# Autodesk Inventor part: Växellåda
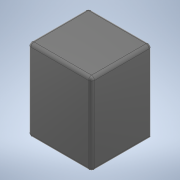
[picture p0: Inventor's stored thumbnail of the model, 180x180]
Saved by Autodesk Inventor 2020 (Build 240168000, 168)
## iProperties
Created: 2019-06
Part Number: Växellåda
Material: Acetal Resin, Black
Document SubType Name: Modeling
Designer: cl
Density: 1.425 g/cm^3
Appearance: Smooth - Black
Author: cl
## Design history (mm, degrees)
sketch "Sketch1"
  geometry: L1 (0, 0)-(0, -135); L2 (0, -135)-(105, -135); L3 (105, -135)-(105, 0); L4 (0, 0)-(105, 0); 1 further point
  constraints: 8 end point, 2 vertical, 1 coincident, 1 horizontal, 1 perpendicular
  dimensions: "d3" = 135 distance of L1.start L1.end; "d4" = 105 distance of L1.end L2.end
extrude "Extrusion1" new body sketch "Sketch1" distance "d5" = 100; taper "d6" = 0 deg
fillet "Fillet1" dims "d7" = 5
body "Solid1"
